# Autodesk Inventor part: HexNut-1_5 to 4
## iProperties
Author: cdotson
Shininess: 100.0
PropertySet Name: _Private Model Information
Created: 2001-02
Part Number: HexNut-1_5 to 4
Material: Steel, Mild
Document SubType Name: Modeling
Designer: cdotson
Description: Heavy Nut, 1 5/8-6 UN
Control State: 0
Master: False
Checked Out: False
PropertySet Name: Design Tracking Control
Density: 7.86
Volumn: 0.06655563914467283
Area: 1.2653523404887146
PropertySet Name: Model Information
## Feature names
1. Extrusion2
2. Revolution1
3. Mirror1
4. Extrusion3
